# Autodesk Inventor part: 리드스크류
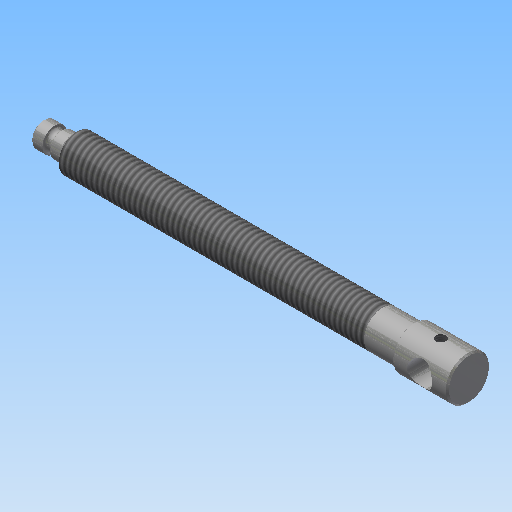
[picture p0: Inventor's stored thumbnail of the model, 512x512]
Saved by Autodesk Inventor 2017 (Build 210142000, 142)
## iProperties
Created: 2019-04
Part Number: 리드스크류
Material: 강철, 연강
Document SubType Name: Modeling
Designer: mduedu
Density: 1 g/cm^3
Appearance: 강철
Author: mduedu
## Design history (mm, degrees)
sketch "스케치1"
  geometry: C1 r 6 at (0, 0); 1 further point
  constraints: 1 centre point, 1 coincident
  dimensions: "d0" = 12 diameter of C1
extrude "돌출1" new body sketch "스케치1" distance "d1" = 110; taper "d2" = 0 deg
sketch "스케치2"
  geometry: C1 r 4 at (0, 0); 1 further point
  constraints: 1 centre point, 1 coincident
  dimensions: "d3" = 8 diameter of C1
extrude "돌출2" join sketch "스케치2" distance "d4" = 10; taper "d5" = 0 deg
sketch "스케치3"
  geometry: C1 r 7 at (0, 0); 1 further point
  constraints: 1 centre point, 1 coincident
  dimensions: "d9" = 14 diameter of C1
extrude "돌출3" join sketch "스케치3" distance "d10" = 18; taper "d11" = 0 deg
feature "스레드1" dims "d12" = 100, "d13" = 0
chamfer "모따기2" distance "d14" = 1; stored, may be unused: second distance "d15" = 2, angle "d16" = 45 deg
chamfer "모따기3" distance "d17" = 0.5; stored, may be unused: second distance "d18" = 2, angle "d19" = 45 deg
chamfer "모따기4" distance "d20" = 0.5; stored, may be unused: second distance "d21" = 2, angle "d22" = 45 deg
sketch "스케치4"
  geometry: L1 (-110, -5)-(-110, 5) reference; L2 (-119.5, 4)-(-119.5, -4) reference; L3 (-119.5, 0)-(-110, 0); C1 r 1.25 at (-115, 4); 1 further point
  constraints: 2 end point, 2 midpoint, 1 centre point
  dimensions: "d23" = 2.5 diameter of C1; "d24" = 5 distance from line of C1.centre L1; "d25" = 4 distance from line of C1.centre L3
revolve "회전1" sketch "스케치4" stored, may be unused: angle "d26" = 90 deg
sketch "스케치5"
  geometry: L1 (0, -6.5)-(0, 6.5) reference; C1 r 4 at (9, 0); 2 further points
  constraints: 1 centre point, 1 horizontal alignment, 1 midpoint
  dimensions: "d27" = 8 diameter of C1; "d28" = 9 distance from line of C1.centre L1
extrude "돌출4" cut sketch "스케치5" stored distance "d29" = 15; taper "d30" = 0 deg
node "작업 평면1"
sketch "스케치6"
  geometry: L1 (0, 6.5)-(0, -6.5) reference; 2 further points
  constraints: 1 horizontal alignment
  dimensions: "d31" = 9 distance from line of point (-9, 0) L1
hole "구멍1" sketch "스케치6" at (-9, 0) diameter "d32" = 3.242; stored, may be unused: countersink angle "d36" = 90 deg, drill point angle "d38" = 118 deg; dims "d33" = 6, "d34" = 4, "d35" = 2, "d37" = 8
node "솔리드1"
